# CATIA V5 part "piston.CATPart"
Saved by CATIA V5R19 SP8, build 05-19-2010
Part number: piston
Bounding box of the stored display mesh (mm): x 0 to 400, y -20 to 20, z -20 to 20
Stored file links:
  U:\Thinkmotion\Assemblage final\piston.CATPart
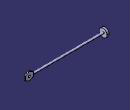
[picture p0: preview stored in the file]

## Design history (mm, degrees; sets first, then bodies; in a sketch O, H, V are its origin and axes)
Body1 (main body)
  Sketch1 on yz-plane, origin (0, 0, 0), H (0, 1, 0), V (0, 0, 1)
    circle A1 centre (0, 0) radius 20
  Pad1: profile Sketch1, direction (1, 0, 0), length 10
  Sketch2 on end face of Pad1, origin (10, 0, 0), H (0, 1, 0), V (0, 0, 1)
    circle A1 centre (0, 0) radius 5
    reference projected circle E1 centre (0, 0) radius 20 from edge [face of Pad1 from Sketch1.A1 | end face of Pad1]
    concentricity: A1 E1
  Pad2: profile Sketch2, direction (1, 0, 0), length 350
  Sketch3 on zx-plane, origin (0, 0, 0), H (-1, 0, 0), V (0, 0, 1)
    point P1 (-360, 0)
    line L1 (-360, 0) -> (-360, 10)
    point P2 (-360, 10)
    line L2 (-360, 10) -> (-380, 20)
    point P3 (-380, 20)
    line L3 (-380, 20) -> (-400, 10)
    point P4 (-400, 10)
    line L4 (-400, 10) -> (-400, 0)
    point P5 (-400, 0)
    reference projected line E1 through (0, 0) direction (-1, 0) from axis of face of Pad2 from Sketch2.A1
    point P8 (-360, 0)
    point P9 (-360, -10)
    point P10 (-380, -20)
    point P11 (-400, -10)
    point P12 (-400, 0)
    line L5 (-360, 0) -> (-360, -10)
    line L6 (-360, -10) -> (-380, -20)
    line L7 (-380, -20) -> (-400, -10)
    line L8 (-400, -10) -> (-400, 0)
    coincidence: P1 H, P5 H, P1 P8, P5 P12
    vertical: L1 V, L4 V
    symmetry: P1 P8 E1, P2 P9 E1, P3 P10 E1, P4 P11 E1, P5 P12 E1, L1 L5 E1, L2 L6 E1, L3 L7 E1, L4 L8 E1
  Pad3: profile Sketch3, direction (0, 1, 0), length 3, mirrored extent
  Sketch4 on start face of Pad3, origin (380.7421, -3, 0), H (1, 0, 0), V (0, 0, 1)
    point P1 (-0.7421, 0)
    reference intersected line E1 through (0, 0) direction (-1, 0) from xy-plane
    reference projected line E2 (-20.7421, 5) -> (-20.7421, -5) from edge [face of Pad2 from Sketch2.A1 | end face of Pad2]
    reference projected line E3 (19.2579, 0) -> (19.2579, -10) from edge [start face of Pad3 | face of Pad3 from Sketch3.L8]
    reference projected line E4 (-20.7421, 0) -> (-20.7421, 10) from edge [start face of Pad3 | face of Pad3 from Sketch3.L1]
    distance E2 E3 = 40 (reference)
    distance P1 E4 = 20
    coincidence: P1 E1
  Hole1: placed by Sketch4, at (380, -3, 0) direction (0, 1, 0), diameter 10, depth 10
